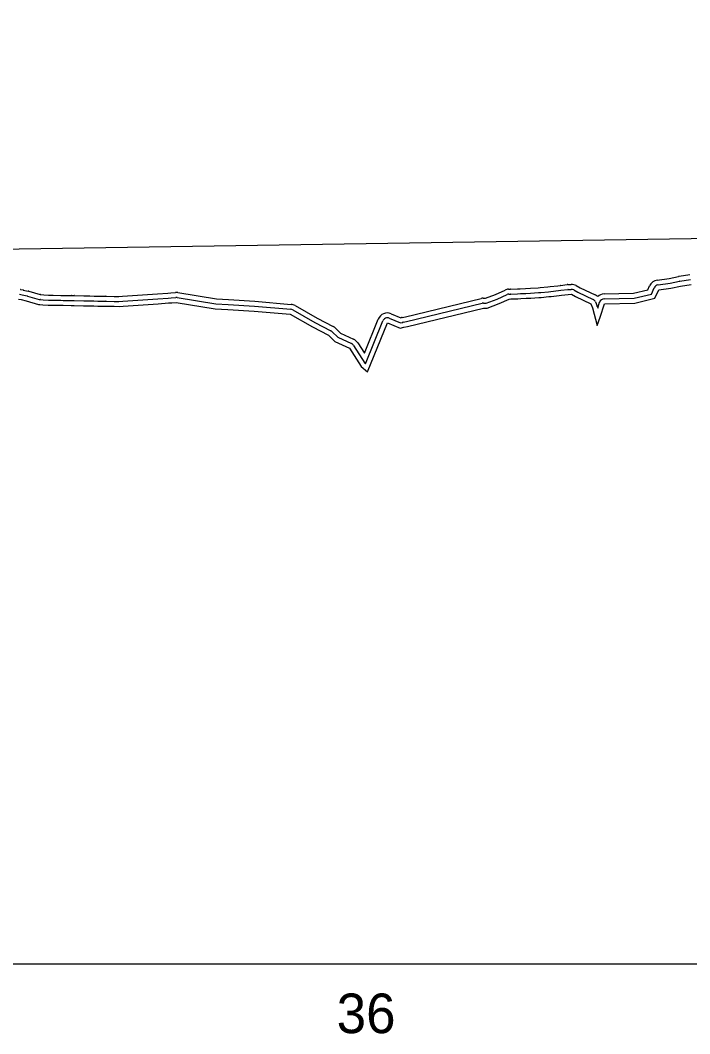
# Model space of a CAD drawing. Extents: x 1625686 to 1640492, y 1161393 to 1175642.
# Drawn here: x 1632716.9 to 1632886, y 1174893.1 to 1175149.2 of the extents above; entities that cross this region are included whole.
import ezdxf

# ---------------------------------------------------------------- set-up
doc = ezdxf.new("R2010")
doc.units = 0
for name, color, linetype in [('Exist Profile Cell', 7, 'Continuous'), ('Exist Vertical Profile Ground Line', 7, 'Continuous'), ('Exist Vertical Profile Horizontal Axis Label Major', 7, 'Continuous'), ('Prop Vertical Profile Grade', 7, 'Continuous'), ('Scratch_Level_1', 7, 'Continuous'), ('Scratch_Level_3', 7, 'Continuous'), ('Scratch_Level_5', 7, 'Continuous')]:
    doc.layers.add(name, color=color, linetype=linetype)

msp = doc.modelspace()

# ---------------------------------------------------------------- linework, layer by layer
at = {"layer": 'Exist Profile Cell'}
msp.add_line((1630204.31, 1174910.79), (1634670.63, 1174910.79), dxfattribs=at)
at = {"layer": 'Exist Vertical Profile Ground Line'}
msp.add_lwpolyline([(1632716.46, 1175078.74), (1632717.1, 1175078.61), (1632718.35, 1175078.31), (1632721.47, 1175077.42), (1632721.87, 1175077.4), (1632722.61, 1175077.32), (1632723.97, 1175077.24), (1632725.18, 1175077.21), (1632727.13, 1175077.19), (1632727.75, 1175077.18), (1632729.76, 1175077.16), (1632730.49, 1175077.14), (1632732.88, 1175077.08), (1632734.37, 1175077.05), (1632735.45, 1175077.02), (1632736.45, 1175076.99), (1632738.02, 1175076.97), (1632738.53, 1175076.97), (1632740.61, 1175076.92), (1632741.88, 1175076.91), (1632742.92, 1175077), (1632751.69, 1175077.59), (1632754.37, 1175077.76), (1632755.14, 1175077.83), (1632756.31, 1175077.92), (1632766.16, 1175076.32), (1632769.35, 1175076.14), (1632775.94, 1175075.69), (1632785.1, 1175074.92), (1632790.68, 1175071.73), (1632794.78, 1175069.6), (1632796.36, 1175068.07), (1632800.03, 1175066.36), (1632802.95, 1175061.73), (1632804.6, 1175060.35), (1632809.62, 1175072.75), (1632812.86, 1175071.42), (1632813.78, 1175071.66), (1632814.7, 1175071.82), (1632833.87, 1175076.47), (1632834.82, 1175076.49), (1632837.83, 1175077.6), (1632840.35, 1175078.75), (1632840.8, 1175078.78), (1632842.56, 1175078.84), (1632843.29, 1175078.87), (1632844.64, 1175078.95), (1632845.86, 1175079.01), (1632847.83, 1175079.13), (1632848.43, 1175079.17), (1632850.39, 1175079.37), (1632850.99, 1175079.44), (1632852.96, 1175079.65), (1632853.56, 1175079.73), (1632855.29, 1175079.91), (1632856.11, 1175079.95), (1632857.15, 1175079.39), (1632861.02, 1175077.55), (1632861.44, 1175076.51), (1632862.57, 1175072.06), (1632863.31, 1175074.17), (1632864.4, 1175077.54), (1632872.13, 1175077.75), (1632877.16, 1175078.94), (1632878.12, 1175081.07), (1632881.21, 1175081.5), (1632883.64, 1175082.03), (1632886.35, 1175082.45)], dxfattribs=at)
at = {"layer": 'Prop Vertical Profile Grade'}
msp.add_line((1632304.31, 1175085.25), (1632929.31, 1175094.7), dxfattribs=at)
at = {"layer": 'Scratch_Level_1'}
for p, q in [((1632883.26, 1175084.5), (1632885.96, 1175084.92)), ((1632883.45, 1175083.27), (1632886.15, 1175083.69)), ((1632716.96, 1175081.19), (1632717.6, 1175081.06)), ((1632717.67, 1175081.04), (1632718.93, 1175080.75)), ((1632742.75, 1175079.5), (1632751.52, 1175080.08)), ((1632754.95, 1175080.33), (1632756.12, 1175080.42)), ((1632840.2, 1175081.24), (1632840.64, 1175081.27)), ((1632853.3, 1175082.22), (1632855.03, 1175082.4)), ((1632853.43, 1175080.97), (1632855.16, 1175081.15)), ((1632855.17, 1175082.41), (1632855.99, 1175082.45)), ((1632855.23, 1175081.16), (1632856.05, 1175081.2)), ((1632716.71, 1175079.97), (1632717.35, 1175079.84)), ((1632717.39, 1175079.83), (1632718.64, 1175079.53)), ((1632729.79, 1175078.41), (1632730.52, 1175078.39)), ((1632729.82, 1175079.66), (1632730.55, 1175079.64)), ((1632742.84, 1175078.25), (1632751.61, 1175078.83)), ((1632755.04, 1175079.08), (1632756.22, 1175079.17)), ((1632769.52, 1175078.63), (1632776.1, 1175078.19)), ((1632776.14, 1175078.19), (1632785.31, 1175077.41)), ((1632840.28, 1175080), (1632840.72, 1175080.02)), ((1632862.18, 1175078.03), (1632862.6, 1175076.98)), ((1632769.44, 1175077.38), (1632776.02, 1175076.94)), ((1632776.04, 1175076.94), (1632785.2, 1175076.17))]:
    msp.add_line(p, q, dxfattribs=at)
for points in [[(1632877.77, 1175083.55), (1632880.77, 1175083.96), (1632883.11, 1175084.47)], [(1632877.95, 1175082.31), (1632880.99, 1175082.73), (1632883.38, 1175083.25)], [(1632719.05, 1175080.72), (1632721.89, 1175079.9), (1632722, 1175079.89)], [(1632751.53, 1175080.08), (1632754.17, 1175080.25), (1632754.9, 1175080.32)], [(1632756.71, 1175080.39), (1632766.44, 1175078.81), (1632769.5, 1175078.63)], [(1632833.82, 1175078.97), (1632834.35, 1175078.98), (1632836.88, 1175079.92), (1632839.32, 1175081.02)], [(1632840.71, 1175081.27), (1632842.46, 1175081.33), (1632843.16, 1175081.37), (1632844.49, 1175081.44)], [(1632840.75, 1175080.02), (1632842.51, 1175080.09), (1632843.23, 1175080.12), (1632844.57, 1175080.19)], [(1632844.51, 1175081.44), (1632845.71, 1175081.51), (1632847.67, 1175081.63), (1632848.22, 1175081.67), (1632850.13, 1175081.86), (1632850.73, 1175081.92), (1632852.66, 1175082.13), (1632853.23, 1175082.21)], [(1632844.57, 1175080.19), (1632845.79, 1175080.26), (1632847.75, 1175080.38), (1632848.32, 1175080.42), (1632850.26, 1175080.62), (1632850.86, 1175080.68), (1632852.81, 1175080.89), (1632853.39, 1175080.97)], [(1632856.71, 1175081.05), (1632857.72, 1175080.5), (1632861.55, 1175078.68)], [(1632857.31, 1175082.15), (1632858.28, 1175081.62), (1632862.09, 1175079.81)], [(1632864.33, 1175080.04), (1632871.8, 1175080.24), (1632875.38, 1175081.09), (1632875.84, 1175082.1)], [(1632864.37, 1175078.79), (1632871.97, 1175079), (1632876.27, 1175080.02), (1632876.98, 1175081.58)], [(1632718.7, 1175079.52), (1632721.68, 1175078.66), (1632721.93, 1175078.64)], [(1632722, 1175078.64), (1632722.71, 1175078.56), (1632724.02, 1175078.49), (1632725.2, 1175078.46), (1632727.15, 1175078.44)], [(1632722.13, 1175079.88), (1632722.81, 1175079.81), (1632724.07, 1175079.74), (1632725.22, 1175079.71), (1632727.16, 1175079.69)], [(1632727.15, 1175078.44), (1632727.76, 1175078.43), (1632729.77, 1175078.41)], [(1632727.17, 1175079.69), (1632727.78, 1175079.68), (1632729.79, 1175079.66)], [(1632730.52, 1175078.39), (1632732.91, 1175078.33), (1632734.4, 1175078.3)], [(1632730.55, 1175079.64), (1632732.94, 1175079.58), (1632734.43, 1175079.55)], [(1632734.41, 1175078.3), (1632735.48, 1175078.27), (1632736.48, 1175078.24), (1632738.03, 1175078.22), (1632738.54, 1175078.22)], [(1632734.44, 1175079.55), (1632735.52, 1175079.51), (1632736.5, 1175079.49), (1632738.04, 1175079.47), (1632738.54, 1175079.47)], [(1632738.56, 1175078.22), (1632740.63, 1175078.17), (1632741.83, 1175078.16), (1632742.81, 1175078.25)], [(1632738.59, 1175079.47), (1632740.65, 1175079.42), (1632741.78, 1175079.41), (1632742.7, 1175079.49)], [(1632751.61, 1175078.83), (1632754.27, 1175079.01), (1632755.02, 1175079.08)], [(1632756.51, 1175079.16), (1632766.3, 1175077.56), (1632769.43, 1175077.38)], [(1632813.35, 1175074.12), (1632814.19, 1175074.27), (1632833.28, 1175078.9)], [(1632813.57, 1175072.89), (1632814.44, 1175073.05), (1632833.58, 1175077.69)], [(1632833.85, 1175077.72), (1632834.58, 1175077.73), (1632837.36, 1175078.76), (1632839.84, 1175079.89)], [(1632862.66, 1175076.82), (1632862.74, 1175076.48), (1632863.21, 1175077.93)], [(1632785.72, 1175076.01), (1632791.27, 1175072.83), (1632795.36, 1175070.71)], [(1632786.34, 1175077.09), (1632791.87, 1175073.93), (1632795.93, 1175071.82)], [(1632810.57, 1175075.06), (1632813.04, 1175074.05), (1632813.16, 1175074.08)], [(1632801.08, 1175067.03), (1632803.9, 1175062.56), (1632804.08, 1175062.41), (1632808.46, 1175073.22)], [(1632802.14, 1175067.7), (1632803.81, 1175065.06), (1632807.31, 1175073.69)], [(1632810.1, 1175073.91), (1632812.95, 1175072.74), (1632813.47, 1175072.87)], [(1632795.65, 1175070.5), (1632797.08, 1175069.12), (1632800.56, 1175067.49)], [(1632796.52, 1175071.4), (1632797.8, 1175070.16), (1632801.08, 1175068.62)]]:
    msp.add_lwpolyline(points, dxfattribs=at)
for centre, radius, start, end in [((1632878.12, 1175081.07), 2.5, 97.8712, 155.793), ((1632883.64, 1175082.03), 2.5, 98.9095, 102.3318), ((1632883.64, 1175082.03), 1.25, 98.9095, 102.3318), ((1632716.46, 1175078.74), 2.5, 78.3717, 79.7394), ((1632717.1, 1175078.61), 2.5, 76.7061, 78.3717), ((1632718.35, 1175078.31), 2.5, 73.9503, 76.7061), ((1632751.69, 1175077.59), 2.5, 93.7115, 93.8158), ((1632755.14, 1175077.83), 2.5, 94.4196, 95.5104), ((1632756.31, 1175077.92), 2.5, 80.7399, 94.4196), ((1632840.35, 1175078.75), 2.5, 93.5392, 114.4462), ((1632840.8, 1175078.78), 2.5, 91.988, 93.5392), ((1632844.64, 1175078.95), 2.5, 93.0224, 93.2987), ((1632844.64, 1175078.95), 1.25, 93.0224, 93.2987), ((1632853.56, 1175079.73), 2.5, 95.9909, 97.7233), ((1632853.56, 1175079.73), 1.25, 95.9909, 97.7233), ((1632855.29, 1175079.91), 2.5, 92.8332, 95.9909), ((1632855.29, 1175079.91), 1.25, 92.8332, 95.9909), ((1632856.11, 1175079.95), 2.5, 61.5289, 92.8332), ((1632856.11, 1175079.95), 1.25, 61.5289, 92.8332), ((1632878.12, 1175081.07), 1.25, 97.8712, 155.793), ((1632717.1, 1175078.61), 1.25, 76.7061, 78.3717), ((1632718.35, 1175078.31), 1.25, 73.9503, 76.7061), ((1632721.87, 1175077.4), 1.25, 83.9447, 86.9867), ((1632721.87, 1175077.4), 2.5, 83.9447, 86.9867), ((1632727.13, 1175077.19), 1.25, 89.1999, 89.2854), ((1632727.13, 1175077.19), 2.5, 89.1999, 89.2854), ((1632729.76, 1175077.16), 1.25, 88.6132, 89.4231), ((1632729.76, 1175077.16), 2.5, 88.6132, 89.4231), ((1632730.49, 1175077.14), 1.25, 88.5278, 88.6132), ((1632730.49, 1175077.14), 2.5, 88.5278, 88.6132), ((1632734.37, 1175077.05), 1.25, 88.3664, 88.6336), ((1632734.37, 1175077.05), 2.5, 88.3664, 88.6336), ((1632738.53, 1175076.97), 2.5, 88.6524, 89.7492), ((1632738.53, 1175076.97), 1.25, 88.6524, 89.7492), ((1632742.92, 1175077), 2.5, 93.8158, 95.0189), ((1632742.92, 1175077), 1.25, 93.8158, 95.0189), ((1632751.69, 1175077.59), 1.25, 93.7115, 93.8158), ((1632755.14, 1175077.83), 1.25, 94.4196, 95.5104), ((1632756.31, 1175077.92), 1.25, 80.7399, 94.4196), ((1632769.35, 1175076.14), 2.5, 86.1568, 86.744), ((1632775.94, 1175075.69), 2.5, 85.1932, 86.1568), ((1632833.87, 1175076.47), 2.5, 91.1484, 103.6241), ((1632833.87, 1175076.47), 1.25, 91.1484, 103.6241), ((1632840.35, 1175078.75), 1.25, 93.5392, 114.4462), ((1632840.8, 1175078.78), 1.25, 91.988, 93.5392), ((1632861.02, 1175077.55), 1.25, 22.1434, 64.6259), ((1632861.02, 1175077.55), 2.5, 47.2664, 64.6259), ((1632864.4, 1175077.54), 2.5, 91.5164, 132.3903), ((1632864.4, 1175077.54), 1.25, 91.5164, 162.0818), ((1632769.35, 1175076.14), 1.25, 86.1568, 86.744), ((1632775.94, 1175075.69), 1.25, 85.1932, 86.1568), ((1632785.1, 1175074.92), 1.25, 60.2283, 85.1932), ((1632785.1, 1175074.92), 2.5, 60.2283, 85.1932), ((1632809.62, 1175072.75), 2.5, 67.6989, 157.9426), ((1632861.44, 1175076.51), 1.25, 14.1628, 22.1434), ((1632809.62, 1175072.75), 1.25, 67.6989, 157.9426), ((1632813.78, 1175071.66), 2.5, 99.9586, 104.4775), ((1632813.78, 1175071.66), 1.25, 99.9586, 104.4775), ((1632794.78, 1175069.6), 1.25, 46.0189, 62.5367), ((1632794.78, 1175069.6), 2.5, 46.0189, 62.5367), ((1632800.03, 1175066.36), 1.25, 32.2752, 64.9384), ((1632800.03, 1175066.36), 2.5, 32.2752, 64.9384)]:
    msp.add_arc(centre, radius, start, end, dxfattribs=at)
at = {"layer": 'Scratch_Level_3'}
msp.add_lwpolyline([(1630204.31, 1174910.79), (1634341.72, 1174910.79), (1634341.72, 1175362.47)], dxfattribs=at)
at = {"layer": 'Scratch_Level_5'}
msp.add_lwpolyline([(1632716.46, 1175078.74), (1632717.1, 1175078.61), (1632718.35, 1175078.31), (1632721.47, 1175077.42), (1632721.87, 1175077.4), (1632722.61, 1175077.32), (1632723.97, 1175077.24), (1632725.18, 1175077.21), (1632727.13, 1175077.19), (1632727.75, 1175077.18), (1632729.76, 1175077.16), (1632730.49, 1175077.14), (1632732.88, 1175077.08), (1632734.37, 1175077.05), (1632735.45, 1175077.02), (1632736.45, 1175076.99), (1632738.02, 1175076.97), (1632738.53, 1175076.97), (1632740.61, 1175076.92), (1632741.88, 1175076.91), (1632742.92, 1175077), (1632751.69, 1175077.59), (1632754.37, 1175077.76), (1632755.14, 1175077.83), (1632756.31, 1175077.92), (1632766.16, 1175076.32), (1632769.35, 1175076.14), (1632775.94, 1175075.69), (1632785.1, 1175074.92), (1632790.68, 1175071.73), (1632794.78, 1175069.6), (1632796.36, 1175068.07), (1632800.03, 1175066.36), (1632802.95, 1175061.73), (1632804.6, 1175060.35), (1632809.62, 1175072.75), (1632812.86, 1175071.42), (1632813.78, 1175071.66), (1632814.7, 1175071.82), (1632833.87, 1175076.47), (1632834.82, 1175076.49), (1632837.83, 1175077.6), (1632840.35, 1175078.75), (1632840.8, 1175078.78), (1632842.56, 1175078.84), (1632843.29, 1175078.87), (1632844.64, 1175078.95), (1632845.86, 1175079.01), (1632847.83, 1175079.13), (1632848.43, 1175079.17), (1632850.39, 1175079.37), (1632850.99, 1175079.44), (1632852.96, 1175079.65), (1632853.56, 1175079.73), (1632855.29, 1175079.91), (1632856.11, 1175079.95), (1632857.15, 1175079.39), (1632861.02, 1175077.55), (1632861.44, 1175076.51), (1632862.57, 1175072.06), (1632863.31, 1175074.17), (1632864.4, 1175077.54), (1632872.13, 1175077.75), (1632877.16, 1175078.94), (1632878.12, 1175081.07), (1632881.21, 1175081.5), (1632883.64, 1175082.03), (1632886.35, 1175082.45)], dxfattribs=at)

# ---------------------------------------------------------------- texts
at = {"layer": 'Exist Vertical Profile Horizontal Axis Label Major'}
msp.add_text('36', height=10, dxfattribs=at).set_placement((1632796.8, 1174893.29))

doc.saveas('drawing.dxf')
